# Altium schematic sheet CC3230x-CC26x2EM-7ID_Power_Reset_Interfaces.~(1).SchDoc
size 431 x 279 mm; Date: Not shown in title block; ApprovedBy: Not shown in title block; CheckedBy: Not shown in title block; Author: Not shown in title block; CompanyName: Not shown in title block; Engineer: Not shown in title block; Organization: Not shown in title block; Address1: Not shown in title block; Address2: Not shown in title block; Address3: Not shown in title block; Address4: Not shown in title block; DocumentNumber: 1; Revision: Use project parameter SCH_Rev; SheetNumber: 1; SheetTotal: 5; PageSetup: Record=PageOptions¦CenterHorizontal=True¦CenterVertical=True¦PrintScale=1.00¦XCorrection=1.00¦YCorrection=1.00¦PrintKind=0¦BorderSize=5000000¦LeftOffset=0¦BottomOffset=0¦Orientation=2¦PaperLength=1000¦PaperWidth=1000¦Scale=100¦PaperSource=15¦PrintQuality=600¦MediaType=1¦DitherType=10¦PaperKind=Letter¦PrintScaleMode=1
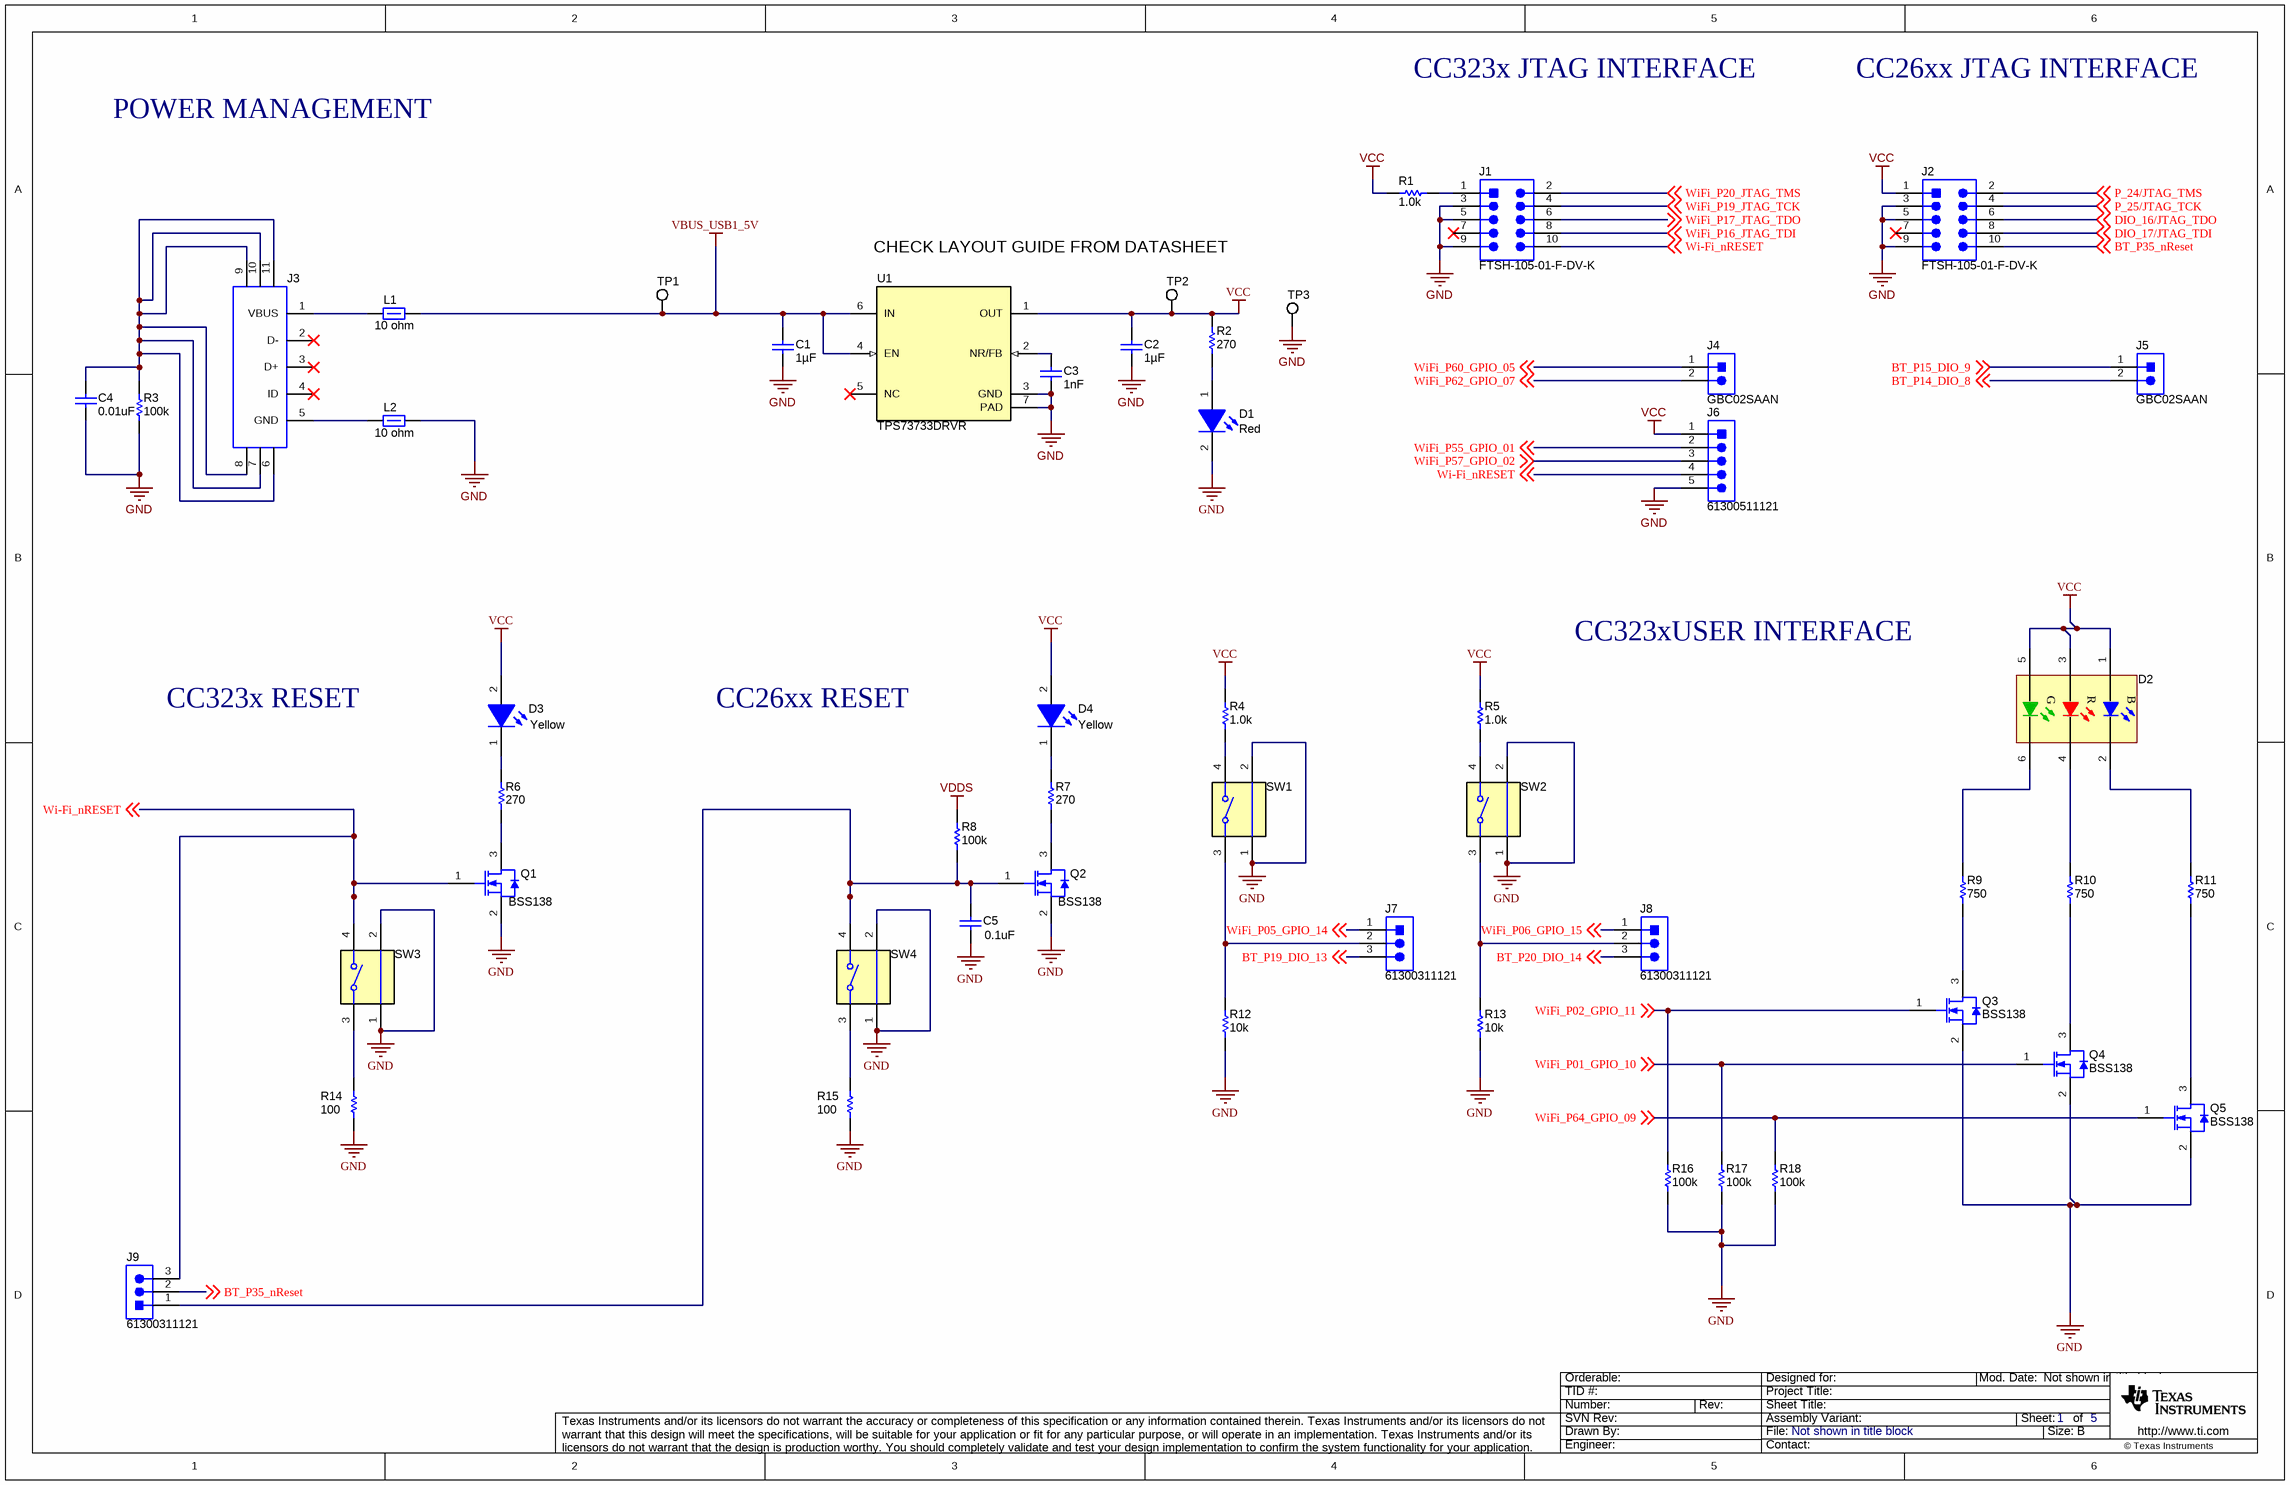
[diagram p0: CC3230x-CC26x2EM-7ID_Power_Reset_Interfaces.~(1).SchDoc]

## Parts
C1  Cap_F: 1µF  [0603]  (hidden comment: GRM188R71E105KA12D)
C2  Cap_F: 1µF  [0603]  (hidden comment: GRM188R71E105KA12D)
C3  Cap_F: 1nF  [0603]  (hidden comment: 06031C102JAT2A)
C4  ValueDisplayed: 0.01uF  [0402]  (hidden comment: C1005X7R1C103K050BA)
C5  ValueDisplayed: 0.1uF  [0201]  (hidden comment: GRM033Z71C104KE14D)
D1  value Red  [19-217_R6C-AL1M2VY_3T_Red]  (hidden comment: 19-217/R6C-AL1M2VY/3T)
D2  EAST1616RGBA8  [EAST1616_RGB]  (value not drawn)
D3  value Yellow  [WL-SMCW_YELLOW]  (hidden comment: 150060YS75000)
D4  value Yellow  [WL-SMCW_YELLOW]  (hidden comment: 150060YS75000)
J1  FTSH-105-01-F-DV-K  [Samtec_FTSH-105-01-x-DV-K]
J2  FTSH-105-01-F-DV-K  [Samtec_FTSH-105-01-x-DV-K]
J3  1051640001  [Molex_1051640001]  (value not drawn)
J4  GBC02SAAN  [Sullins_Gxx02SAAN]
J5  GBC02SAAN  [Sullins_Gxx02SAAN]
J6  61300511121  [Wurth_61300511121]
J7  61300311121  [WURTH_61300311121]
J8  61300311121  [WURTH_61300311121]
J9  61300311121  [WURTH_61300311121]
L1  ValueDisplayed: 10 ohm  [0402]  (hidden comment: CMP-0003309-1)
L2  ValueDisplayed: 10 ohm  [0402]  (hidden comment: CMP-0003309-1)
Q1  PartNumber: BSS138  [SOT-23]  (hidden comment: CMP-0000755-1)
Q2  PartNumber: BSS138  [SOT-23]  (hidden comment: CMP-0000755-1)
Q3  BSS138  [SOT-23]
Q4  BSS138  [SOT-23]
Q5  BSS138  [SOT-23]
R1  ValueDisplayed: 1.0k  [0402]  (hidden comment: CRCW04021K00JNED)
R2  ValueDisplayed: 270  [0603]  (hidden comment: CMP-0025765-4)
R3  ValueDisplayed: 100k  [0603]  (hidden comment: CMP-0025698-4)
R4  ValueDisplayed: 1.0k  [0402]  (hidden comment: CMP-0026852-3)
R5  ValueDisplayed: 1.0k  [0402]  (hidden comment: CMP-0026852-3)
R6  ValueDisplayed: 270  [0603]  (hidden comment: CMP-0025765-4)
R7  ValueDisplayed: 270  [0603]  (hidden comment: CMP-0025765-4)
R8  ValueDisplayed: 100k  [0201]  (hidden comment: RC0201JR-7D100KL)
R9  ValueDisplayed: 750  [0603]  (hidden comment: RC0603JR-07750RL)
R10  ValueDisplayed: 750  [0603]  (hidden comment: RC0603JR-07750RL)
R11  ValueDisplayed: 750  [0603]  (hidden comment: RC0603JR-07750RL)
R12  ValueDisplayed: 10k  [0402]  (hidden comment: CMP-0026825-5)
R13  ValueDisplayed: 10k  [0402]  (hidden comment: CMP-0026825-5)
R14  ValueDisplayed: 100  [0402]  (hidden comment: CMP-0026656-1)
R15  ValueDisplayed: 100  [0402]  (hidden comment: CMP-0026656-1)
R16  ValueDisplayed: 100k  [0402]  (hidden comment: CMP-0026823-3)
R17  ValueDisplayed: 100k  [0402]  (hidden comment: CMP-0026823-3)
R18  ValueDisplayed: 100k  [0402]  (hidden comment: CMP-0026823-3)
SW1  CMP-0002328-1  [SW_1188E]  (value not drawn)
SW2  CMP-0002328-1  [SW_1188E]  (value not drawn)
SW3  CMP-0002328-1  [SW_1188E]  (value not drawn)
SW4  CMP-0002328-1  [SW_1188E]  (value not drawn)
TP1  5015  [Testpoint_Keystone_Miniature]  (value not drawn)
TP2  5015  [Testpoint_Keystone_Miniature]  (value not drawn)
TP3  5015  [Testpoint_Keystone_Miniature]  (value not drawn)
U1  TPS73733DRVR  [DRV0006A]

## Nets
GND: C1.2 C2.2 C3.2 C4.2 C5.2 D1.2(K) J1.3 J1.5 J1.9 J2.3 J2.5 J2.9 J6.5 L2.2 Q1.2(S) Q2.2(S) Q3.2(S) Q4.2(S) Q5.2(S) R3.1 R12.2 R13.2 R14.1 R15.1 R16.2 R17.2 R18.2 SW1.1 SW1.2 SW2.1 SW2.2 SW3.1 SW3.2 SW4.1 SW4.2 TP3.1 U1.3(GND) U1.7(PAD)
VBUS_USB1_5V: C1.1 L1.2 TP1.1 U1.4(EN) U1.6(IN)
VCC: C2.1 D2.1(A) D2.3(A) D2.5(A) D3.2(A) D4.2(A) J2.1 J6.1 R1.1 R2.1 R4.1 R5.1 TP2.1 U1.1(OUT)
VDDS: R8.2
BT_P14_DIO_8: J5.2 ; off-sheet BT_P14_DIO_8
BT_P15_DIO_9: J5.1 ; off-sheet BT_P15_DIO_9
BT_P19_DIO_13: J7.3 ; off-sheet BT_P19_DIO_13
BT_P20_DIO_14: J8.3 ; off-sheet BT_P20_DIO_14
BT_P35_nReset: J2.10 J9.2 ; off-sheet BT_P35_nReset
DIO_16/JTAG_TDO: J2.6 ; off-sheet DIO_16/JTAG_TDO
DIO_17/JTAG_TDI: J2.8 ; off-sheet DIO_17/JTAG_TDI
P_24/JTAG_TMS: J2.2 ; off-sheet P_24/JTAG_TMS
P_25/JTAG_TCK: J2.4 ; off-sheet P_25/JTAG_TCK
Wi-Fi_nRESET: J1.10 J6.4 J9.3 Q1.1(G) SW3.4 ; off-sheet Wi-Fi_nRESET
WiFi_P01_GPIO_10: Q4.1(G) R17.1 ; off-sheet WiFi_P01_GPIO_10
WiFi_P02_GPIO_11: Q3.1(G) R16.1 ; off-sheet WiFi_P02_GPIO_11
WiFi_P05_GPIO_14: J7.1 ; off-sheet WiFi_P05_GPIO_14
WiFi_P06_GPIO_15: J8.1 ; off-sheet WiFi_P06_GPIO_15
WiFi_P16_JTAG_TDI: J1.8 ; off-sheet WiFi_P16_JTAG_TDI
WiFi_P17_JTAG_TDO: J1.6 ; off-sheet WiFi_P17_JTAG_TDO
WiFi_P19_JTAG_TCK: J1.4 ; off-sheet WiFi_P19_JTAG_TCK
WiFi_P20_JTAG_TMS: J1.2 ; off-sheet WiFi_P20_JTAG_TMS
WiFi_P55_GPIO_01: J6.2 ; off-sheet WiFi_P55_GPIO_01
WiFi_P57_GPIO_02: J6.3 ; off-sheet WiFi_P57_GPIO_02
WiFi_P60_GPIO_05: J4.1 ; off-sheet WiFi_P60_GPIO_05
WiFi_P62_GPIO_07: J4.2 ; off-sheet WiFi_P62_GPIO_07
WiFi_P64_GPIO_09: Q5.1(G) R18.1 ; off-sheet WiFi_P64_GPIO_09
NetC3_1: C3.1 U1.2(NR/FB)
NetC4_1: C4.1 J3.6 J3.7 J3.8 J3.9 J3.10 J3.11 R3.2
NetC5_1: C5.1 J9.1 Q2.1(G) R8.1 SW4.4
NetD1_1: D1.1(A) R2.2
NetD2_2: D2.2(K) R11.2
NetD2_4: D2.4(K) R10.2
NetD2_6: D2.6(K) R9.2
NetD3_1: D3.1(K) R6.2
NetD4_1: D4.1(K) R7.2
NetJ1_1: J1.1 R1.2
NetJ3_1: J3.1(VBUS) L1.1
NetJ3_5: J3.5(GND) L2.1
NetJ7_2: J7.2 R12.1 SW1.3
NetJ8_2: J8.2 R13.1 SW2.3
NetQ1_3: Q1.3(D) R6.1
NetQ2_3: Q2.3(D) R7.1
NetQ3_3: Q3.3(D) R9.1
NetQ4_3: Q4.3(D) R10.1
NetQ5_3: Q5.3(D) R11.1
NetR4_2: R4.2 SW1.4
NetR5_2: R5.2 SW2.4
NetR14_2: R14.2 SW3.3
NetR15_2: R15.2 SW4.3

Not connected (* = marked no-connect by the designer): J1 7*; J2 7*; J3 2(D-)* 3(D+)* 4(ID)*; U1 5(NC)*

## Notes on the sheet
- CC323x JTAG INTERFACE
- CC26xx JTAG INTERFACE
- POWER MANAGEMENT
- CHECK LAYOUT GUIDE FROM DATASHEET
- CC323xUSER INTERFACE
- CC323x RESET
- CC26xx RESET

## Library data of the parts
C1 C2 = CMP-0007405-4: CAP, CERM, 1 uF, 25 V, +/- 10%, X7R, 0603; Manufacturer: MuRata; TaMin_C: -55°C; Polarized: N; SizeAreaWB_mm2: 4.68; Value1: Unknown; U/M: EA; Value: 1uF; TaMax_C: 125°C; SizeZ_mm: 1; SizeX_mm: 1.6; SizeY_mm: 0.8; Value2: 25V; SizeArea_mm2: 1.28; CompType: Capacitor; AEC Category: Q200
C3 = CMP-0006723-4: CAP, CERM, 1000 pF, 100 V, +/- 5%, X7R, 0603; Manufacturer: AVX; TaMin_C: -55°C; ESR_ohm: 2.76d; Polarized: N; SizeAreaWB_mm2: 4.68; Value1: 0.276 ohm; U/M: EA; Value: 1000pF; TaMax_C: 125°C; SizeZ_mm: 1; SizeX_mm: 1.6; SizeY_mm: 0.8; Value2: 100V; SizeArea_mm2: 1.28; CompType: Capacitor; AEC Category: Q200
C4 = CMP-0006292-2: CAP, CERM, 0.01 uF, 16 V, +/- 10%, X7R, 0402; Manufacturer: TDK; Alternate PartNumber: 0402B103K500CT; Alternate Manufacturer: Walsin; Polarized: N; CompType: Capacitor; Value: 0.01uF; U/M: EA; Cap_F: 10nF; ESR_ohm: 0.0623; Value1: 0.0623 ohm; VDC_V: 16V; TaMin_C: -55°C; TaMax_C: 125°C; AEC Category: Q200; SizeAreaWB_mm2: 3; SizeZ_mm: 0.6; SizeX_mm: 1; SizeY_mm: 0.5
C5 = CMP-0064970-1: CAP, CERM, 0.1 uF, 16 V,+/- 10%, X7R, 0201; Manufacturer: MuRata; TaMin_C: -55°C; Polarized: N; SizeAreaWB_mm2: 2.08; Value1: Unknown; U/M: EA; Value: 0.1uF; TaMax_C: 125°C; SizeZ_mm: 0.26; SizeX_mm: 0.6; SizeY_mm: 0.3; Value2: 16V; SizeArea_mm2: 0.18; CompType: Capacitor; Cap_F: 100nF; AEC Category: Q200
D1 = CMP-0086159-1: LED, Red, SMD; Manufacturer: Everlight; SizeArea_mm2: 1.28; Tjmax_C: 85°C; Angle: 120; SizeZ_mm: 0.5; Value1: 0.06W; Ir_A: 10µA; SizeX_mm: 1.6; Io_A: 5mA; Vf_V: 1.95V; SizeY_mm: 0.8; Vr_V: 5V; Power_TotalModule: 60mW; SizeAreaWB_mm2: 4.68
D2 = CMP-0003017-3: LED, RGB, SMD; Manufacturer: Everlight; SizeZ_mm: 0.45; Io_A: 25mA; SizeY_mm: 1.6; Type: InGaN; Ir_A: 50µA; Vr_V: 5V; Value2: 3.7V; SizeAreaWB_mm2: 6.76; SizeArea_mm2: 2.56; Angle: 120; Tjmax_C: 85°C
D3 D4 = CMP-0002892-3: LED, Yellow, SMD; Manufacturer: Wurth Elektronik; Value1: W; Vf_V: 2V; Type: AlInGaP; Io_A: 20mA
J1 J2 = CMP-0075670-2: Header (Shrouded), 1.27mm, 5x2, Gold, SMT; Manufacturer: Samtec; Pitch_mm: 1.27; Gender: Male; Cert_CSA: Y; Current_A: 3.3A; Row_Count: 2
J3 = CMP-0055311-1: Receptacle, USB 2.0, Micro B, 5 Position, R/A, SMT; Manufacturer: Molex; CNHeader: FALSE; Current_A: 1.8A; Gender: Female; Voltage_V: 30V; Pitch_mm: 0.65; ContactFinish: Gold; CT: TRUE; Cert_UL: Y
J4 J5 = CMP-0054576-1: Header, 2.54 mm, 2x1, Gold, TH; Manufacturer: Sullins Connector Solutions; CT: FALSE; CNHeader: TRUE
J6 = CMP-0084909-1: Header, 2.54mm, 5x1, Gold, TH; Manufacturer: Wurth Elektronik; Pitch_mm: 2.54; Gender: Male; Row_Count: 1; Shrouded: N; Current_A: 3A; Voltage_V: 250V
J7-J9 = CMP-0054796-2: Header, 2.54 mm, 3x1, Gold, TH; Manufacturer: Wurth Elektronik; Pitch_mm: 2.54; Green_Lifecycle: Active; Cert_UL: Y; Shrouded: N; Green_REACh: Passed; Gender: Male; Row_Count: 1
L1 L2 = CMP-0003309-1: Ferrite Bead, 10 ohm @ 100 MHz, 1 A, 0402; PartNumber: BLM15AG100SN1D; Manufacturer: MuRata; Alternate PartNumber: ----; Value: 10 ohm; Imax_A: 1A; DCR_ohm: 0.025; Value1: 0.025 ohm; ZTyp@100MHz_Ohm: 10; SizeAreaWB_mm2: 3; SizeZ_mm: 0.6; SizeX_mm: 1; SizeY_mm: 0.5
Q1 Q2 = CMP-0000755-1: MOSFET, N-CH, 50 V, 0.22 A, SOT-23; Manufacturer: Fairchild Semiconductor; Alternate Manufacturer: ON; Alternate PartNumber: BSS138LT1G; U/M: EA; ChType: N; Value: 50V; Rdson45_ohm: 6; Value2: 1.7 nC; QgTyp_nC: 1.7; Vgs_V: 20V; IdsMax_A: 2.2dA; SizeZ_mm: 1.1; SizeX_mm: 2.5; SizeY_mm: 3; SizeArea_mm2: 7.5; AEC Category: Q101; SizeAreaWB_mm2: 14
Q3-Q5 = CMP-0000755-1: MOSFET, N-CH, 50 V, 0.22 A, SOT-23; Alternate Manufacturer: None; Manufacturer: Fairchild Semiconductor; SizeZ_mm: 1.1; ChType: N; Value2: 1.7 nC; VdsMax_V: 50V; SizeX_mm: 2.5; SizeY_mm: 3; Vgs_V: 20V; Value: 50V; Rdson45_ohm: 6; SizeArea_mm2: 7.5; AEC Category: Q101; IdsMax_A: 2.2dA; SizeAreaWB_mm2: 14; U/M: EA; QgTyp_nC: 1.7
R1 = CMP-0026852-3: RES, 1.0 k, 5%, 0.063 W, AEC-Q200 Grade 0, 0402; Manufacturer: Vishay-Dale; Power_W: 63mW; TempCo: 200 ppm/C; Value_Code: 1k00; Value: 1.0k; EIA_Code: E24; Res_ohm: 1k; SizeX_mm: 1; SizeY_mm: 0.5; SizeZ_mm: 0.6; Value2: 0.063W; AEC Qualified: Y; VDC_V: 50V; AEC Category: Q200; AEC Grade: 0
R2 = CMP-0025765-4: RES, 270, 5%, 0.1 W, AEC-Q200 Grade 0, 0603; PartNumber: CRCW0603270RJNEA; Manufacturer: Vishay-Dale; Alternate Manufacturer: YAGEO; Alternate PartNumber: RC0603JR-07270RL; Value: 270; Value_Code: 270R; Power_W: 100mW; Value2: 0.1W; VDC_V: 75V; TempCo: 200 ppm/C; EIA_Code: E24; SizeX_mm: 1.6; SizeY_mm: 0.8; SizeZ_mm: 1; SizeArea_mm2: 1.28; AEC Qualified: Y; AEC Category: Q200; AEC Grade: 0
R3 = CMP-0025698-4: RES, 100 k, 5%, 0.1 W, AEC-Q200 Grade 0, 0603; PartNumber: CRCW0603100KJNEA; Manufacturer: Vishay-Dale; Alternate Manufacturer: YAGEO; Alternate PartNumber: RC0603JR-07100KL; CompType: Resistor; Value: 100k; Power_W: 100mW; Value2: 0.1W; VDC_V: 75V; TempCo: 200 ppm/C; EIA_Code: E24; AEC Category: Q200; AEC Qualified: Y; AEC Grade: 0; SizeX_mm: 1.6; SizeY_mm: 0.8; SizeZ_mm: 1; SizeArea_mm2: 1.28
R4 R5 = CMP-0026852-3: RES, 1.0 k, 5%, 0.063 W, AEC-Q200 Grade 0, 0402; PartNumber: CRCW04021K00JNED; Manufacturer: Vishay-Dale; Alternate Manufacturer: YAGEO; Alternate PartNumber: RC0402JR-071KL; Value: 1.0k; Res_ohm: 1k; Value_Code: 1k00; Power_W: 63mW; Value2: 0.063W; VDC_V: 50V; TempCo: 200 ppm/C; EIA_Code: E24; SizeX_mm: 1; SizeY_mm: 0.5; SizeZ_mm: 0.6; AEC Qualified: Y; AEC Category: Q200; AEC Grade: 0
R6 R7 = CMP-0025765-4: RES, 270, 5%, 0.1 W, AEC-Q200 Grade 0, 0603; PartNumber: CRCW0603270RJNEA; Manufacturer: Vishay-Dale; Alternate Manufacturer: YAGEO; Alternate PartNumber: RC0603JR-07270RL; CompType: Resistor; Value: 270; Value_Code: 270R; Power_W: 100mW; Value2: 0.1W; VDC_V: 75V; TempCo: 200 ppm/C; EIA_Code: E24; SizeX_mm: 1.6; SizeY_mm: 0.8; SizeZ_mm: 1; SizeArea_mm2: 1.28; AEC Qualified: Y; AEC Category: Q200; AEC Grade: 0
R8 = CMP-0027184-1: RES, 100 k, 5%, 0.05 W, 0201; Manufacturer: Yageo America; Power_W: 50mW; TempCo: 200 ppm/C; U/M: EA; Value: 100k; EIA_Code: E24; SizeX_mm: 0.6; SizeY_mm: 0.3; SizeZ_mm: 0.26; Value2: 0.05W; SizeArea_mm2: 0.18; CompType: Resistor; AEC Qualified: N; VDC_V: 25V; AEC Category: Q200
R9-R11 = CMP-0025939-5: RES, 750, 5%, 0.1 W, 0603; Manufacturer: Yageo; Power_W: 100mW; TempCo: 100 ppm/C; Value_Code: 750R; Value: 750; EIA_Code: E24; SizeX_mm: 1.6; SizeY_mm: 0.8; SizeZ_mm: 1; Value2: 0.1W; SizeArea_mm2: 1.28; AEC Qualified: N; VDC_V: 75V; AEC Category: Q200; SizeAreaWB_mm2: 4.68
R12 R13 = CMP-0026825-5: RES, 10 k, 5%, 0.063 W, AEC-Q200 Grade 0, 0402; PartNumber: CRCW040210K0JNED; Manufacturer: Vishay-Dale; Alternate Manufacturer: YAGEO; Alternate PartNumber: RC0402JR-0710KL; Value: 10k; Value_Code: 10k0; Power_W: 63mW; Value2: 0.063W; VDC_V: 50V; TempCo: 200 ppm/C; EIA_Code: E24; SizeX_mm: 1; SizeY_mm: 0.5; SizeZ_mm: 0.6; AEC Qualified: Y; AEC Category: Q200; AEC Grade: 0
R14 R15 = CMP-0026656-1: RES, 100, 1%, 0.1 W, 0402; PartNumber: ERJ-2RKF1000X; Manufacturer: Panasonic; Alternate Manufacturer: YAGEO; Alternate PartNumber: RC0402FR-07100RL; CompType: Resistor; Value: 100; Value_Code: 100R; Power_W: 100mW; Value2: 0.1W; VDC_V: 50V; TempCo: 100 ppm/C; EIA_Code: E96; U/M: EA; SizeX_mm: 1; SizeY_mm: 0.5; SizeZ_mm: 0.6; AEC Category: Q200
R16-R18 = CMP-0026823-3: RES, 100 k, 5%, 0.063 W, AEC-Q200 Grade 0, 0402; PartNumber: CRCW0402100KJNED; Manufacturer: Vishay-Dale; Alternate Manufacturer: YAGEO; Alternate PartNumber: RC0402JR-07100KL; Value: 100k; Power_W: 63mW; Value2: 0.063W; VDC_V: 50V; TempCo: 200 ppm/C; EIA_Code: E24; SizeArea_mm2: 0.5; SizeX_mm: 1; SizeZ_mm: 0.6; AEC Category: Q200; AEC Qualified: Y; AEC Grade: 0
SW1-SW4 = CMP-0002328-1: Switch, SPST, 0.05 A, 12 VDC, SMD; PartNumber: 1188E-1K2-V-TR; Manufacturer: Diptronics; Alternate Manufacturer: ----; VDC_V: 12V; PositionCount: 1; CurrentRating_mA: 50A; SizeAreaWB_mm2: 53.9; SizeArea_mm2: 27.3; SizeX_mm: 7.8; SizeY_mm: 3.5
TP1-TP3 = CMP-0055152-1: Test Point, Miniature, SMT; Manufacturer: Keystone; CNHeader: FALSE; Green_Lifecycle: Active; Green_REACh: Passed; CT: TRUE
U1 = CMP-0073832-5: Single Output LDO, 1A, Adj. (1.2 to 5.0V), Reverse Current Protection, DRV0006A (WSON-6); Manufacturer: Texas Instruments; Alternate PartNumber: TPS73733DRVT; SizeX_mm: 2; CompType: IC; SizeZ_mm: 0.8; SizeArea_mm2: 4; SizeAreaWB_mm2: 9; Green_Lifecycle: Active; Green_REACh: Passed; AEC Category: Q200; AEC Qualified: N; Rating: Catalog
